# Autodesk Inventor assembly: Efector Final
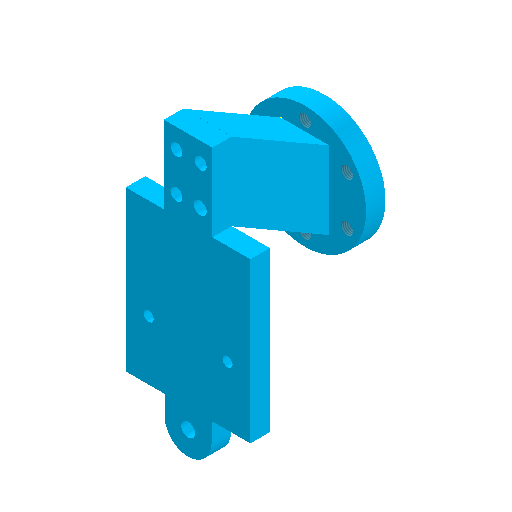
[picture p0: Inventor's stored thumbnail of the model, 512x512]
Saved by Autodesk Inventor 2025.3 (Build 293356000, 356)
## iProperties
Created: 2026-01
Part Number: Efector Final
Document SubType Name: Assembly
Designer: Dell
Author: Dell
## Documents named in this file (3)
- C:\Users\Dell\Downloads\TESIS FINAL\CAD Final\Efector Final.iam
- C:\Users\Dell\Downloads\TESIS FINAL\CAD Final\Acople_Extructor_3_v2.ipt
- C:\Users\Dell\Downloads\TESIS FINAL\CAD Final\Acople_Extructor.ipt
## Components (2 placed, 2 different names)
1. Acople_Extructor_3_v2:1 — Insertar:1
2. Acople_Extructor:1 — Insertar:1
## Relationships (1: Insert 1)
- Insertar:1: Acople_Extructor_3_v2:1 ↔ Acople_Extructor:1
